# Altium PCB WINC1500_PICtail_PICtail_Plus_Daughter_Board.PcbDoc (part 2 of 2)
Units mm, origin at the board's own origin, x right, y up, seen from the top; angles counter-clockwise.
Board outline 40 x 55.01 mm, 2 copper layers (Top Layer, Bottom Layer), stack 1.571 mm thick; 57 components, 48 nets, 242 pads, 214 vias.
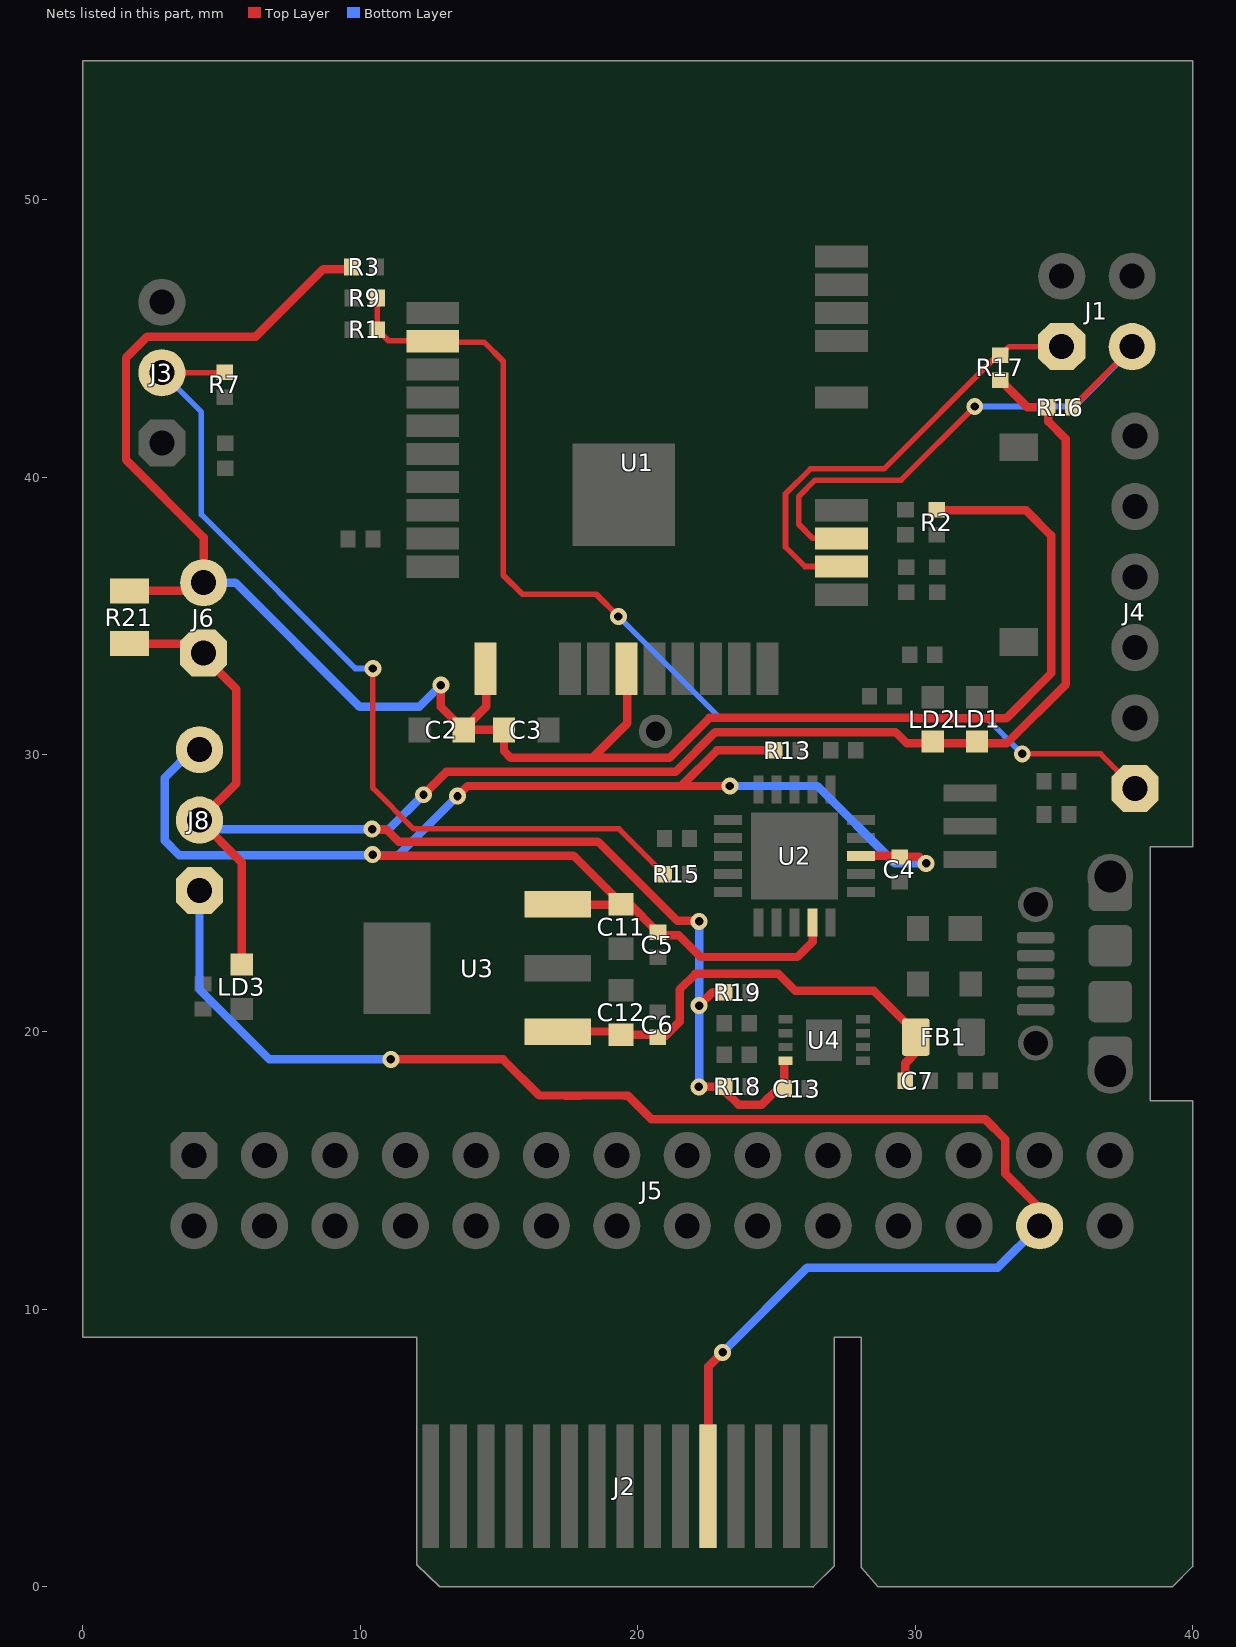
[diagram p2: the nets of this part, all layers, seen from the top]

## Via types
v1: diameter 0.61, hole 0.305, Top Layer to Bottom Layer, 214 vias

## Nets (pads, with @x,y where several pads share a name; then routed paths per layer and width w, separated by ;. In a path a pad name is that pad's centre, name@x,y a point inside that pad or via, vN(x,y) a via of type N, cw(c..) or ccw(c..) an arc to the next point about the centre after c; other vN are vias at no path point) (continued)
USB_UART_TXD: J3.2 R7.1 R15.1 | length 32.5
  Top Layer w0.203: J3.2@2.845,43.764 R7.1@5.087,43.764 ; v1(10.45,33.1) 10.45,28.79 11.92,27.32 19.321,27.32 R15.1@20.962,25.679
  Bottom Layer w0.203: J3.2@2.845,43.764 4.267,42.342 4.267,38.646 9.813,33.1 v1(10.45,33.1)
VCC_BASE_BOARD_3V3: J2.21 J2.22 J5.26 J8.1 | length 61.9
  Top Layer w0.305: v1(11.1,19.009) 15.147,19.009 16.449,17.707 17.376,17.707 17.379,17.704 17.927,17.704 17.93,17.707 19.514,17.707 19.522,17.7 19.65,17.7 20.5,16.85 32.525,16.85 33.25,16.125 33.25,14.885 34.483,13.652 J5.26@34.483,13.01 ; J2.21@22.542,3.603 22.542,7.937 v1(23.055,8.45)
  Bottom Layer w0.305: J8.1@4.2,25.095 4.2,21.53 6.721,19.009 v1(11.1,19.009) ; J2.22@22.542,3.603 22.542,7.937 v1(23.055,8.45) 26.106,11.501 32.974,11.501 J5.26@34.483,13.01
VCC_MODULE_3V3: C2.2 C3.2 J6.2 R2.2 R3.2 R21.1 U1.20 U1.23 | length 73.6
  Top Layer w0.305: R21.1@1.525,35.9 R21.1@1.675,35.9 4.055,35.9 J6.2@4.35,36.195 4.35,37.825 1.55,40.625 1.55,44.3 2.31,45.06 6.223,45.06 8.661,47.498 9.608,47.498 R3.2@9.685,47.574 ; v1(12.9,32.5) 12.9,31.715 C2.2@13.729,30.886 ; U1.20@14.539,33.103 14.539,31.735 13.729,30.924 C2.2@13.729,30.886 ; U1.23@19.619,33.103 19.619,31.125 18.377,29.883 ; R2.2@30.785,38.804 33.996,38.804 34.9,37.9 34.9,32.921 33.287,31.309 30.085,31.309 30.076,31.318 22.581,31.318 21.143,29.88 18.38,29.88 18.377,29.883 ; C2.2@13.729,30.886 C3.2@15.177,30.886 15.177,30.123 15.417,29.883 18.377,29.883
  Bottom Layer w0.305: J6.2@4.225,36.195 J6.2@4.35,36.195 5.497,36.195 9.977,31.715 12.115,31.715 v1(12.9,32.5)
VCC_TARGET_3V3: C13.2 J6.1 J8.2 LD1.1 LD2.1 LD3.1 R16.2 R17.2 R18.2 R19.2 R21.2 U4.8 | length 87
  Top Layer w0.305: R21.2@1.525,34 R21.2@1.675,34 3.88,34 5.525,32.355 5.525,28.96 J8.2@4.2,27.635 5.725,26.11 LD3.1@5.725,22.425 ; v1(10.422,27.313) 10.455,27.28 10.958,27.28 11.374,26.863 18.562,26.863 21.425,24 22.195,24 v1(22.212,23.983) ; v1(12.275,28.55) 13.097,29.372 21.354,29.372 22.792,30.81 29.29,30.81 29.7,30.4 33.296,30.4 35.425,32.529 35.425,41.375 34.8,42 34.8,42.52 R16.2@34.78,42.52 34.043,42.52 R17.2@33.071,43.492 ; v1(22.205,18.021) 23.135,18.021 R18.2@23.146,18.032 23.146,17.855 23.624,17.377 24.468,17.377 25.049,17.958 C13.2@25.28,17.958 U4.8@25.28,18.942 ; v1(22.212,20.947) 22.701,21.436 R19.2@23.146,21.436
  Bottom Layer w0.305: J8.2@4.2,27.635 4.522,27.313 v1(10.422,27.313) 10.455,27.28 10.998,27.28 12.269,28.55 v1(12.275,28.55) ; v1@22.212,18.021 v1(22.212,20.947) v1(22.212,23.983)
VCC_USB_3V3: C4.2 C5.2 C11.2 J8.3 R13.2 U2.14 U2.18 U3.3 | length 60.2
  Top Layer w0.305: v1(10.442,26.388) 10.475,26.355 17.676,26.355 C11.2@19.406,24.625 ; v1(13.5,28.5) 13.864,28.864 21.564,28.864 ; U3.3@17.124,24.449 17.262,24.587 19.368,24.587 C11.2@19.406,24.625 ; v1(23.317,28.864) 21.564,28.864 ; R13.2@24.95,30.15 22.85,30.15 21.564,28.864 ; U2.14@26.298,23.675 26.298,23.248 25.751,22.7 22.264,22.7 21.472,23.492 20.824,23.492 C5.2@20.726,23.589 19.691,24.625 C11.2@19.406,24.625 ; U2.18@28.049,26.343 C4.2@29.403,26.343 ; C4.2@29.439,26.307 30.152,26.307
  Bottom Layer w0.305: J8.3@4.2,30.175 3.957,30.175 2.95,29.168 2.95,26.892 3.467,26.375 10.506,26.375 10.526,26.355 11.355,26.355 v1(13.5,28.5) ; v1(23.317,28.864) 26.475,28.864 29.261,26.078 v1(30.396,26.078)
VCC_USB_5V0: C6.1 C7.1 C12.2 FB1.2 U3.1 | length 18.5
  Top Layer w0.305: U3.1@16.21,20.015 C12.2@19.355,20.015 ; C12.2@19.355,19.901 20.619,19.901 20.701,19.819 20.962,19.819 21.509,20.366 21.509,21.527 22.073,22.092 25.066,22.092 25.669,21.488 28.499,21.488 FB1.2@30.023,19.964 ; C7.1@29.642,18.237 29.642,18.872 30.099,19.329 30.099,19.736 FB1.2@30.023,19.812 FB1.2@30.023,19.964 ; FB1.2@30.023,20.117 FB1.2@30.023,19.964
WAKE: J4.1 R1.2 R9.1 U1.11 | length 39.8
  Top Layer w0.203: R9.1@10.61,46.457 R1.2@10.61,45.314 11.01,44.914 12.634,44.914 12.692,44.856 14.469,44.856 15.15,44.175 15.15,36.463 15.838,35.775 18.5,35.775 v1(19.3,34.975) ; v1(33.858,30.023) 36.678,30.023 J4.1@37.922,28.778
  Bottom Layer w0.203: v1(19.3,34.975) 22.909,31.366 32.515,31.366 v1(33.858,30.023)
WINC_I2C_SCL: J1.1 R17.1 U1.2 | length 16.4
  Top Layer w0.203: U1.2@27.34,36.776 26.024,36.776 25.325,37.475 25.325,39.4 26.222,40.297 28.87,40.297 32.965,44.392 R17.1@33.071,44.392 33.383,44.704 J1.1@35.281,44.704 ; U1.2@27.362,36.798 U1.2@27.407,36.754
WINC_I2C_SDA: J1.3 R16.1 U1.3 | length 20.2
  Top Layer w0.203: U1.3@27.34,37.792 26.308,37.792 25.8,38.3 25.8,39.3 26.391,39.891 29.491,39.891 v1(32.145,42.545) ; U1.3@27.34,37.802 U1.3@27.366,37.802 ; R16.1@35.68,42.52 37.821,44.66 J1.3@37.821,44.704
  Bottom Layer w0.203: v1(32.145,42.545) 35.753,42.545 37.821,44.613 J1.3@37.821,44.704
pads on no net: J1.4 J2.2 J2.4 J2.11 J2.12 J2.13 J2.17 J2.19 J2.20 J2.23 J2.24 J2.25 J2.26 J2.27 J2.29 J5.1 J5.2 J5.3 J5.4 J5.5 J5.6 J5.7 J5.9 J5.13 J5.14 J5.15 J5.16 J5.17 J5.18 J5.19 J5.20 J5.21 J5.22 J7.4 U1.5 U1.6 U1.7 U1.8 U2.2 U2.3 U2.4 U2.5 U2.6 U2.8 U2.10 U2.11 U2.12 U2.13 U4.1 U4.2 U4.3 U4.7
copper on no net: | length 10.6
  Bottom Layer w0.203: 0.35,12.809 2.15,12.809 2.15,16.292 0.35,16.292 0.35,12.809

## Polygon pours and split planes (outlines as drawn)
GND on Top Layer "Top Layer - GND" (solid, remove dead copper, pour order 2): 0.086,48.625 0.086,8.98 11.331,8.98 11.331,8.979 11.331,8.086 27.051,8.086 27.051,8.98 40.086,8.98 40.086,48.625
GND on Bottom Layer "Bottom Layer - GND" (solid, remove dead copper, pour order 3): 10.926,8.025 10.951,8.059 26.648,8.059 26.648,8.94 26.674,8.915 39.653,8.915 39.653,48.89 -0.327,48.89 -0.327,8.94 10.9,8.94

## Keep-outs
Keep-Out Layer:
  lines w0.102: 39.699,54.7 0.3,54.7 0.3,9.289 12.029,9.289 12.029,0.79 12.863,0 26.284,0 27.043,0.759 27.043,8.989 28.36,8.989 28.36,0.931 28.925,0.366 39.144,0.366 39.7,0.922 39.7,17.526 38.475,17.526 38.475,26.675 39.7,26.675 39.7,54.7
  text ".Layer_Name" at 249.4,-103.5 h1.5

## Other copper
Top Layer:
  pour cut-out: 0,55 0,48.625 40,48.625 40,55
  text ".Layer_Name" at 260.787,-101.585 h1.5
  text ".ProjectRevisionART" at 281.957,-103.706 h1.5
Bottom Layer:
  pour cut-out: 0,55 0,48.625 40,48.625 40,55
  text "04-10608 REV" at 1.85,30.55 h1.2 r90
  text ".ProjectRevisionART" at 1.798,15.949 h1.2 r90
  text ".Layer_Name" at -25.926,-101.686 h1.5
  text ".ProjectRevisionART" at -48.783,-103.602 h1.5
  text ".ProjectRevisionART" at 281.957,-103.706 h1.5
  text ".ProjectRevisionART" at 281.957,-103.706 h1.5
  text ".ProjectRevisionART" at 281.957,-103.706 h1.5

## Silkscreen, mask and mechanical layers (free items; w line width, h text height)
Top Overlay:
  text "WINC1500 PICtail™/" at 1.025,53.275 h1.27
  text "PICtail Plus" at 1.025,51.875 h1.27
  text "Daughter Board" at 1.025,50.425 h1.52
  text "M" at 30.607,49.886 h3.81
  text "1" at 33.325,45.225 h0.51
  text "1" at 0.85,40.875 h0.51
  text "1" at 6.269,33.256 h0.51
  text "USB" at 0.998,29.845 h0.51
  text "1" at 37.79,26.566 h0.51
  text "BB" at 1.433,24.844 h0.51
  text "1" at 6.279,24.547 h0.51
  text "11" at 16.34,17.097 h0.51
  text "1" at 3.851,17.089 h0.51
  text "27" at 38.603,15.651 h0.51
  text ".ProjectPartNumber" at 2.08,15.397 h1.2 r90
  text "28" at 38.603,12.72 h0.51
  text "11" at 17.239,6.327 h0.51
  text "21" at 22.233,6.223 h0.51
  text ".Layer_Name" at 249.4,-103.5 h1.5
  text ".ProjectRevisionART" at 281.957,-103.706 h1.5
Bottom Overlay:
  text "C" at 38.8,49.1 h10
  text "" at 4.7,46.85 h10
  text "e" at 20.975,46.85 h10
  text "" at 11.6,46.05 h10
  text "12" at 17.882,6.317 h0.51
  text "22" at 22.964,6.215 h0.51
  text ".Layer_Name" at -15.939,-103.602 h1.5
  text ".ProjectRevisionART" at 281.957,-103.706 h1.5
Top Paste:
  text ".Layer_Name" at 249.4,-103.5 h1.5
  text ".ProjectRevisionART" at 281.957,-103.706 h1.5
Bottom Paste:
  text ".Layer_Name" at -16.096,-103.607 h1.5
  text ".ProjectRevisionART" at 281.957,-103.706 h1.5
Top Solder:
  text ".Layer_Name" at 260.789,-101.6 h1.5
  text ".ProjectRevisionART" at 281.957,-103.706 h1.5
Bottom Solder:
  text ".Layer_Name" at -25.885,-101.73 h1.5
  text ".ProjectRevisionART" at 281.957,-103.706 h1.5
NOTES (M1):
  text ".Layer_Name" at 267.4,-103.5 h1.5
BOARD (M2):
  lines w0.102: 0,27.863 0,55 40,55 40,26.675 38.475,26.675 38.475,17.526 39.997,17.526 39.997,0.726 39.271,0 28.662,0 28.06,0.683 28.06,8.989 27.078,8.989 27.078,0.751 26.317,-0.01 ; 0,27.864 0,8.989 12.029,8.989 12.029,0.79 12.857,0 ; 12.862,0 26.317,0
  text ".Layer_Name" at 267.195,-103.535 h1.5
  text ".ProjectRevisionART" at 281.957,-103.706 h1.5
REF POINTS (M3):
  text ".Layer_Name" at 249.4,-103.5 h1.5
FAB (M4):
  drawing of 320 lines, arcs and shapes, not listed
  text "THIS PCB TO BE MANUFACTURED TO MEET ALL ACCEPTANCE LEVELS" at 186.037,91.802 h1.78
  text "OF A CLASS 2 PCB PER ANSI/IPC-A-600G." at 186.037,87.992 h1.78
  text "MATERIAL:" at 186.037,83.372 h1.78
  text "FR-4 or Equivalent" at 206.357,83.372 h1.78
  text "CONTROLLED IMPEDANCE" at 262.548,79.14 h1.78
  text "MULTILAYER" at 212.072,79.022 h1.78
  text "2" at 235.567,79.022 h1.78
  text "LAYERS" at 240.012,79.022 h1.78
  text "Cu WEIGHT EXTERNAL LAYERS" at 206.357,74.172 h1.78
  text "35um" at 258.427,74.172 h1.78
  text "FINISHED" at 267.952,74.172 h1.78
  text "Cu WEIGHT INTERNAL LAYERS" at 206.357,69.322 h1.78
  text "N/A" at 258.427,69.322 h1.78
  text "FINISHED" at 267.952,69.322 h1.78
  text "FINISHED OVERALL THICKNESS" at 206.357,64.472 h1.78
  text "1.6" at 259.697,64.472 h1.78
  text "mm" at 267.952,64.472 h1.78
  text "10" at 282.557,64.472 h1.78
  text "%" at 290.812,64.472 h1.78
  text "COPPER THIEVING ALLOWED" at 206.548,59.64 h1.78
  text "YES" at 263.548,59.64 h1.78
  text "NO" at 280.548,59.64 h1.78
  text "X" at 275.139,59.14 h2.6
  text "FINISH:" at 186.048,55.14 h1.78
  text "LEAD-FREE HOT AIR LEVELING" at 212.048,54.84 h1.78
  text "IMMERSION GOLD" at 212.072,49.302 h1.78
  text "X" at 207.092,48.984 h2.6
  text "IMMERSION TIN" at 212.072,43.802 h1.78
  text "SMOBC WITH SELECTIVE GOLD PLATING ON LANDS" at 212.072,40.097 h1.78
  text "INDICATED. 1um GOLD OVER 5-10 um NICKEL" at 212.072,36.287 h1.78
  text "SOLDERMASK" at 206.357,29.452 h1.78
  text "DYNACHEM EPIC 200 LPI OR EQUIVALENT" at 227.947,29.452 h1.78
  text "SOLDERMASK COLOR" at 206.357,23.102 h1.78
  text "GREEN HIGH GLOSS" at 238.107,23.102 h1.78
  text "SILKSCREEN COLOR" at 206.357,16.752 h1.78
  text "WHITE" at 238.107,16.752 h1.78
  text "ALL HOLES TO BE LOCATED BY THE COORDINATES FROM THE NC DRILL DATA PROVIDED." at 186.037,10.402 h1.78
  text "05-" at 218.048,4.14 h1.78
  text ".ProjectBoardNumber" at 223.048,4.14 h1.78
  text "PCB REV" at 254.048,4.14 h1.78
  text "USE ARTWORK SET NO." at 186.037,4.052 h1.78
  text ".ProjectRevisionART" at 267.198,3.89 h1.78
  text "ALL UL LOGO, MANUFACTURER'S ID, AND DATE CODES SHALL BE PLACED" at 186.037,-2.298 h1.78
  text "ON THE BOTTOM SIDE UNLESS OTHERWISE INDICATED." at 186.037,-6.108 h1.78
  text "ANY ALTERNATIVES TO THE ABOVE SPECIFICATIONS MUST FIRST BE APPROVED." at 185.548,-11.36 h1.78
  text "Layer" at 181.451,-17.018 h1.52
  text "Name" at 191.863,-17.018 h1.52
  text "Material" at 215.478,-17.018 h1.52
  text "Thickness" at 237.316,-17.018 h1.52
  text "Constant" at 253.822,-17.018 h1.52
  text "Board Layer Stack" at 268.297,-17.018 h1.52
  text "1" at 181.451,-20.066 h1.52
  text "Top Paste" at 191.863,-20.066 h1.52
  text "2" at 181.451,-23.114 h1.52
  text "Top Overlay" at 191.863,-23.114 h1.52
  text "3" at 181.451,-26.162 h1.52
  text "Top Solder" at 191.863,-26.162 h1.52
  text "Solder Resist" at 215.478,-26.162 h1.52
  text "0.010mm" at 237.316,-26.162 h1.52
  text "3.5" at 253.822,-26.162 h1.52
  text "4" at 181.451,-29.21 h1.52
  text "Top Layer" at 191.863,-29.21 h1.52
  text "Copper" at 215.478,-29.21 h1.52
  text "0.036mm" at 237.316,-29.21 h1.52
  text "5" at 181.451,-32.258 h1.52
  text "Dielectric1" at 191.863,-32.258 h1.52
  text "FR-4" at 215.478,-32.258 h1.52
  text "1.500mm" at 237.316,-32.258 h1.52
  text "4.6" at 253.822,-32.258 h1.52
  text "6" at 181.451,-35.306 h1.52
  text "Bottom Layer" at 191.863,-35.306 h1.52
  text "Copper" at 215.478,-35.306 h1.52
  text "0.036mm" at 237.316,-35.306 h1.52
  text "7" at 181.451,-38.354 h1.52
  text "Bottom Solder" at 191.863,-38.354 h1.52
  text "Solder Resist" at 215.478,-38.354 h1.52
  text "0.010mm" at 237.316,-38.354 h1.52
  text "3.5" at 253.822,-38.354 h1.52
  text "8" at 181.451,-41.402 h1.52
  text "Bottom Overlay" at 191.863,-41.402 h1.52
  text "9" at 181.451,-44.45 h1.52
  text "Bottom Paste" at 191.863,-44.45 h1.52
  text ".Layer_Name" at 249.4,-103.5 h1.5
  text ".ProjectRevisionFAB" at 281.957,-103.706 h1.5
Case (M5):
  text ".Layer_Name" at 249.4,-103.5 h1.5
Cover (M6):
  text ".Layer_Name" at 249.4,-103.5 h1.5
Terminal Block (M7):
  text ".Layer_Name" at 249.4,-103.5 h1.5
Milling (M8):
  text ".Layer_Name" at 249.4,-103.5 h1.5
V-Cut (M9):
  text ".Layer_Name" at 249.4,-103.5 h1.5
Assy BOT (M10):
  text ".variantName" at -0.805,-87.65 h0.9
  text "ASSEMBLY VARIANT:" at 13.445,-87.65 h0.9
  text "DOCUMENT NUMBER:" at -32.825,-95.9 h1.14
  text "-D" at -46.825,-98.9 h1.78
  text ".ProjectBoardNumber" at -38.575,-98.9 h1.78
  text "02-" at -33.075,-98.9 h1.78
  text ".ProjectRevisionASSY" at -48.659,-103.622 h1.5
  text ".Layer_Name" at -14.875,-103.65 h1.5
Assy TOP (M11):
  text "ASSEMBLY NOTES:" at -21.552,-53.96 h4
  text "1. ALL COMPONENTS SHALL BE RoHS COMPLIANT." at -55.652,-59.06 h3
  text "2. ALL UNUSED THROUGH HOLE COMPONENT LOCATIONS SHALL BE FREE OF SOLDER." at -55.652,-62.06 h3
  text "3. ALL COMPONENTS SHALL BE MOUNTED FLUSH TO THE BOARD, EXCEPT AS NOTED." at -55.652,-65.06 h3
  text "4. FINISHED BOARD SHALL BE FREE OF ALL RESIDUES." at -55.652,-68.06 h3
  text "5. ALL LEADS SHALL BE TRIMMED TO A MAXIMUM HEIGHT OF 2mm" at -55.652,-71.06 h3
  text "6. PLACE LABEL  ON THE LOCATION INDICATED." at -55.652,-74.06 h3
  text "ASSEMBLY VARIANT:" at 221.4,-87.5 h0.9
  text ".variantName" at 235.65,-87.5 h0.9
  text "DOCUMENT NUMBER:" at 267.65,-95.75 h1.14
  text "02-" at 267.9,-98.75 h1.78
  text ".ProjectBoardNumber" at 273.4,-98.75 h1.78
  text "-D" at 281.65,-98.75 h1.78
  text ".Layer_Name" at 249.4,-103.5 h1.5
  text ".ProjectRevisionASSY" at 281.957,-103.706 h1.5
3D BOT (M12):
  text ".Layer_Name" at -15.7,-103.685 h1.5
3D TOP (M13):
  text ".Layer_Name" at 249.4,-103.5 h1.5
Guard BOT (M14):
  text ".Layer_Name" at -15.667,-103.607 h1.5
  text ".ProjectRevisionART" at 281.957,-103.706 h1.5
Guard TOP (M15):
  text ".Layer_Name" at 249.4,-103.5 h1.5
  text ".ProjectRevisionART" at 281.957,-103.706 h1.5
TITLE (M16):
  lines w0.1: 220.9,-86.25 302.72,-86.25 ; 277.9,-78.75 277.9,-81.75 302.72,-81.75 ; 291.44,-103.385 291.44,-102.115 ; 291.44,-102.75 301.6,-102.75 ; 291.6,-101.55 291.6,-100.55 ; 291.6,-101.05 301.6,-101.05 ; 293.98,-103.385 293.98,-102.115 ; 296.52,-103.385 296.52,-102.115 ; 296.6,-101.35 296.6,-100.75 ; 299.06,-103.385 299.06,-102.115 ; 301.6,-103.385 301.6,-102.115 ; 301.6,-101.55 301.6,-100.55 ; 302.72,-81.75 302.72,-81.75
  lines w0.127: -73.052,-49.035 -67.972,-49.035 ; -73.052,11.29 -67.972,11.29 ; -73.052,71.615 -67.972,71.615 ; -9.552,-109.36 -9.552,-104.28 ; -9.552,126.86 -9.552,131.94 ; 53.948,-109.36 53.948,-104.28 ; 53.948,126.86 53.948,131.94 ; 117.448,-109.36 117.448,-104.28 ; 117.448,126.86 117.448,131.94 ; 153.008,-104.28 188.568,-104.28 ; 180.948,-109.36 180.948,-104.28 ; 180.948,126.86 180.948,131.94 ; 186.9,-104.17 186.9,-78.75 302.72,-78.75 ; 220.9,-104.17 220.9,-78.75 ; 220.9,-99.75 302.72,-99.75 ; 220.9,-93.75 302.72,-93.75 ; 220.9,-87.75 302.72,-87.75 ; 244.448,-109.36 244.448,-104.28 ; 244.448,126.86 244.448,131.94 ; 248.9,-104.17 248.9,-87.75 ; 266.9,-99.75 266.9,-93.75 ; 279.9,-104.17 279.9,-99.75 ; 287.4,-104.17 287.4,-93.75 ; 302.868,-49.035 307.948,-49.035 ; 302.868,11.29 307.948,11.29 ; 302.868,71.615 307.948,71.615 ; -73.052,-109.36 -73.052,131.94 307.948,131.94 307.948,-109.36 -73.052,-109.36 ; -67.972,-104.28 -67.972,126.86 302.868,126.86 302.868,-104.28 -67.972,-104.28
  lines w0.254: 181.048,126.64 181.048,122.14 ; 192.048,117.64 192.048,122.14 192.048,126.64 ; 192.05,113.185 192.05,117.685 ; 192.103,105.486 192.103,113.405 ; 204.548,117.64 204.548,122.14 204.548,126.64 ; 204.568,105.585 204.568,113.405 ; 204.586,113.373 204.586,117.873 ; 283.048,117.64 283.048,122.14 283.048,126.64 ; 283.065,113.223 283.065,117.723 ; 283.106,105.628 283.106,113.349 ; 302.548,117.64 181.048,117.64 181.048,122.14 ; 302.548,122.14 181.048,122.14 ; 302.789,105.4 181.046,105.4 181.046,113.258 302.789,113.258 ; 302.809,113.223 181.018,113.223 181.018,117.723 302.809,117.723
  text "1" at -41.776,128.638 h1.78
  text "2" at 21.613,128.638 h1.78
  text "3" at 84.843,128.638 h1.78
  text "4" at 148.512,128.638 h1.78
  text "5" at 211.986,128.638 h1.78
  text "6" at 275.613,128.638 h1.78
  text "REV" at 183.548,123.64 h1.52
  text "ECO" at 193.548,123.64 h1.52
  text "Comments" at 240.048,123.14 h1.52
  text "Date" at 288.048,123.14 h1.52
  text "1" at 183.311,119.289 h1.52
  text "Initial revision" at 206.357,119.299 h1.52
  text "12/10/2016" at 285.034,119.225 h1.52
  text "-" at 195.315,119.078 h1.52
  text "Component ID of U1 updated" at 206.568,114.983 h1.52
  text "1.1" at 183.573,114.872 h1.52
  text "19/10/2016" at 285.105,114.838 h1.52
  text "-" at 195.209,114.763 h1.52
  text "Mechanical boundary of board near J2 modified" at 206.253,110.561 h1.52
  text "1.2" at 183.553,110.407 h1.52
  text "-" at 195.42,110.338 h1.52
  text "30/11/2016" at 285.176,109.301 h1.52
  text "R22 and R23 are populated in production" at 206.197,107.536 h1.52
  text "A" at -71.147,99.606 h1.78
  text "B" at -71.147,39.154 h1.78
  text "B" at 304.773,39.154 h1.78
  text "C" at -71.147,-21.171 h1.78
  text "C" at 304.773,-21.171 h1.78
  text "PART NUMBER:" at 278.9,-80.75 h1
  text ".ProjectpartNumber" at 290.9,-81 h1.5
  text "TITLE:" at 221.9,-81.25 h1.14
  text "D" at -71.147,-81.369 h1.78
  text "D" at 304.773,-81.369 h1.78
  text ".ProjectTitle" at 221.9,-85.25 h2.5
  text "PCB DESIGNER:" at 221.9,-89.75 h1.14
  text "GERBER FILE:" at 249.9,-89.75 h1.14
  text ".ProjectDrawnBy" at 221.9,-92.75 h1.78
  text ".Plot_File_Name" at 249.9,-92.75 h1.5
  text "M" at 189.9,-94.75 h15.24
  text "ENGINEER:" at 221.9,-95.75 h1.14
  text "BOARD NUMBER:" at 249.9,-95.75 h1.14
  text "DATE:" at 288.6,-95.75 h1.14
  text "Microchip Technology Inc." at 188.67,-98.01 h1.78
  text ".ProjectEngineer" at 221.9,-98.75 h1.78
  text "04-" at 249.9,-98.75 h1.78
  text ".ProjectBoardNumber" at 254.9,-98.75 h1.78
  text ".PRINT_DATE" at 288.6,-98.75 h1.5
  text "2355 W. Chandler Blvd." at 189.9,-100.75 h1.78
  text "LAYER NAME:" at 249.9,-101.25 h1.14
  text "10mm" at 287.9,-101.35 h0.7
  text "PCB FILE NAME:" at 221.9,-101.5 h1.14
  text "REV:" at 280.65,-101.5 h1.14
  text "400mil" at 287.8,-103.05 h0.7
  text "Chandler, AZ  85224" at 190.9,-103.25 h1.78
  text ".PCB_FILE_NAME_NO_PATH" at 221.9,-103.5 h1.14
  text "1" at -41.776,-107.582 h1.78
  text "2" at 21.613,-107.582 h1.78
  text "3" at 84.843,-107.582 h1.78
  text "4" at 148.512,-107.582 h1.78
  text "5" at 211.986,-107.582 h1.78
  text "6" at 275.613,-107.582 h1.78
Drill Drawing:
  lines w0.254: 69.536,-33.019 69.853,-33.019 69.853,-33.337 70.488,-33.337 70.488,-33.019 70.806,-33.019 70.806,-32.384 70.488,-32.384 70.488,-32.067 69.853,-32.067 69.853,-32.384 69.536,-32.384 69.536,-33.019 ; 69.536,-29.209 69.853,-29.209 70.171,-29.527 70.488,-29.209 70.806,-29.209 70.488,-28.892 70.806,-28.574 70.488,-28.574 70.171,-28.257 69.853,-28.574 69.536,-28.574 69.853,-28.892 69.536,-29.209 ; 69.536,-25.717 70.171,-25.399 70.806,-25.717 70.488,-25.082 70.806,-24.447 70.171,-24.764 69.536,-24.447 69.853,-25.082 69.536,-25.717 ; 69.536,-20.637 70.806,-20.637 70.171,-21.907 69.536,-20.637 ; 69.536,-18.097 70.806,-18.097 70.806,-16.827 69.536,-16.827 69.536,-18.097 ; 69.79,-17.843 70.552,-17.843 70.552,-17.081 69.79,-17.081 69.79,-17.843
  lines w0.381: 67.805,-34.48 166.331,-34.48 ; 67.805,-15.43 166.331,-15.43 ; 81.798,-38.29 81.798,-11.62 ; 99.522,-38.29 99.522,-11.62 ; 133.7,-38.29 133.7,-11.62 ; 146.55,-38.29 146.55,-11.62 ; 67.805,-38.29 166.331,-38.29 166.331,-11.62 67.805,-11.62 67.805,-38.29
  text "Symbol" at 70.091,-14.287 h1.83
  text "Hit Count" at 82.941,-14.287 h1.83
  text "Finished Hole Size" at 100.665,-14.287 h1.83
  text "Plated" at 134.843,-14.287 h1.83
  text "Hole Type" at 147.693,-14.287 h1.83
  text "1" at 82.941,-18.097 h1.52
  text "0.700mm (27.56mil)" at 100.665,-18.097 h1.52
  text "PTH" at 134.843,-18.097 h1.52
  text "Round" at 147.693,-18.097 h1.52
  text "2" at 82.941,-21.907 h1.52
  text "0.889mm (35.00mil)" at 100.665,-21.907 h1.52
  text "PTH" at 134.843,-21.907 h1.52
  text "Round" at 147.693,-21.907 h1.52
  text "2" at 82.941,-25.717 h1.52
  text "1.143mm (45.00mil)" at 100.665,-25.717 h1.52
  text "PTH" at 134.843,-25.717 h1.52
  text "Round" at 147.693,-25.717 h1.52
  text "46" at 82.941,-29.527 h1.52
  text "0.900mm (35.43mil)" at 100.665,-29.527 h1.52
  text "PTH" at 134.843,-29.527 h1.52
  text "Round" at 147.693,-29.527 h1.52
  text "214" at 82.941,-33.337 h1.52
  text "0.305mm (12.00mil)" at 100.665,-33.337 h1.52
  text "PTH" at 134.843,-33.337 h1.52
  text "Round" at 147.693,-33.337 h1.52
  text "265 Total" at 82.941,-37.147 h1.52
  text "DOCUMENT NUMBER:" at 267.65,-95.75 h1.14
  text "04-" at 267.9,-98.75 h1.78
  text ".ProjectBoardNumber" at 273.4,-98.75 h1.78
  text "-D" at 281.65,-98.75 h1.78
  text ".ProjectRevisionFAB" at 281.957,-103.706 h1.5
TITLE MIRROR (M17):
  lines w0.1: -67.875,-86.4 13.945,-86.4 ; -66.775,-103.535 -66.775,-102.265 ; -66.775,-102.9 -56.615,-102.9 ; -66.775,-101.7 -66.775,-100.7 ; -66.775,-101.2 -56.775,-101.2 ; -64.235,-103.535 -64.235,-102.265 ; -61.775,-101.5 -61.775,-100.9 ; -61.695,-103.535 -61.695,-102.265 ; -59.155,-103.535 -59.155,-102.265 ; -56.775,-101.7 -56.775,-100.7 ; -56.615,-103.535 -56.615,-102.265 ; -43.055,-78.9 -43.055,-81.9 -67.875,-81.9 ; -67.875,-81.9 -67.875,-81.9
  lines w0.127: -73.052,-49.035 -67.972,-49.035 ; -73.052,11.29 -67.972,11.29 ; -73.052,71.615 -67.972,71.615 ; -67.895,-99.9 13.925,-99.9 ; -67.895,-93.9 13.925,-93.9 ; -67.875,-87.9 13.945,-87.9 ; -67.875,-78.9 47.945,-78.9 47.945,-104.32 ; -52.575,-104.32 -52.575,-93.9 ; -45.075,-104.32 -45.075,-99.9 ; -32.075,-99.9 -32.075,-93.9 ; -14.055,-104.32 -14.055,-87.9 ; -9.552,-109.36 -9.552,-104.28 ; -9.552,126.86 -9.552,131.94 ; 13.945,-104.32 13.945,-78.9 ; 53.948,-109.36 53.948,-104.28 ; 53.948,126.86 53.948,131.94 ; 117.448,-109.36 117.448,-104.28 ; 117.448,126.86 117.448,131.94 ; 180.948,-109.36 180.948,-104.28 ; 180.948,126.86 180.948,131.94 ; 244.448,-109.36 244.448,-104.28 ; 244.448,126.86 244.448,131.94 ; 302.868,-49.035 307.948,-49.035 ; 302.868,11.29 307.948,11.29 ; 302.868,71.615 307.948,71.615 ; -73.052,-109.36 307.948,-109.36 307.948,131.94 -73.052,131.94 -73.052,-109.36 ; -67.972,-104.28 302.868,-104.28 302.868,126.86 -67.972,126.86 -67.972,-104.28
  text "6" at -40.718,128.638 h1.78
  text "5" at 22.909,128.638 h1.78
  text "4" at 86.383,128.638 h1.78
  text "3" at 150.052,128.638 h1.78
  text "2" at 213.282,128.638 h1.78
  text "1" at 276.672,128.638 h1.78
  text "A" at -69.877,99.606 h1.78
  text "B" at -69.877,39.154 h1.78
  text "B" at 306.043,39.154 h1.78
  text "C" at -69.877,-21.171 h1.78
  text "C" at 306.043,-21.171 h1.78
  text "PART NUMBER:" at -44.055,-80.9 h1
  text "TITLE:" at 12.945,-80.9 h1.14
  text ".ProjectpartNumber" at -56.055,-81.15 h1.5
  text "D" at -69.877,-81.369 h1.78
  text "D" at 306.043,-81.369 h1.78
  text ".ProjectTitle" at 12.945,-85.4 h2.5
  text "GERBER FILE:" at -15.055,-89.9 h1.14
  text "PCB DESIGNER:" at 12.945,-89.9 h1.14
  text ".Plot_File_Name" at -15.055,-92.9 h1.5
  text ".ProjectDrawnBy" at 12.945,-92.9 h1.78
  text "M" at 44.945,-94.9 h15.24
  text "DATE:" at -53.775,-95.9 h1.14
  text "BOARD NUMBER:" at -15.075,-95.9 h1.14
  text "ENGINEER:" at 12.925,-95.9 h1.14
  text "Microchip Technology Inc." at 46.175,-98.16 h1.78
  text ".PRINT_DATE" at -53.775,-98.9 h1.5
  text ".ProjectBoardNumber" at -20.075,-98.9 h1.78
  text "04-" at -15.075,-98.9 h1.78
  text ".ProjectEngineer" at 12.925,-98.9 h1.78
  text "2355 W. Chandler Blvd." at 44.945,-100.9 h1.78
  text "LAYER NAME:" at -15.075,-101.4 h1.14
  text "10mm" at -53.075,-101.5 h0.7
  text "REV:" at -45.825,-101.65 h1.14
  text "PCB FILE NAME:" at 12.925,-101.65 h1.14
  text "400mil" at -52.975,-103.2 h0.7
  text "Chandler, AZ  85224" at 43.945,-103.4 h1.78
  text ".PCB_FILE_NAME_NO_PATH" at 12.925,-103.65 h1.14
  text "6" at -40.718,-107.582 h1.78
  text "5" at 22.909,-107.582 h1.78
  text "4" at 86.383,-107.582 h1.78
  text "3" at 150.052,-107.582 h1.78
  text "2" at 213.282,-107.582 h1.78
  text "1" at 276.672,-107.582 h1.78

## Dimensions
0,8.989 to 12.863,0 on BOARD (M2)
0,8.989 to 39.997,0.726 on BOARD (M2)
39.271,0 to 40,55 on BOARD (M2)
28.06,0.683 to 39.997,0.726 on BOARD (M2)
12.029,0.79 to 27.078,0.751 on BOARD (M2)
27.078,0.751 to 28.06,0.683 on BOARD (M2)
